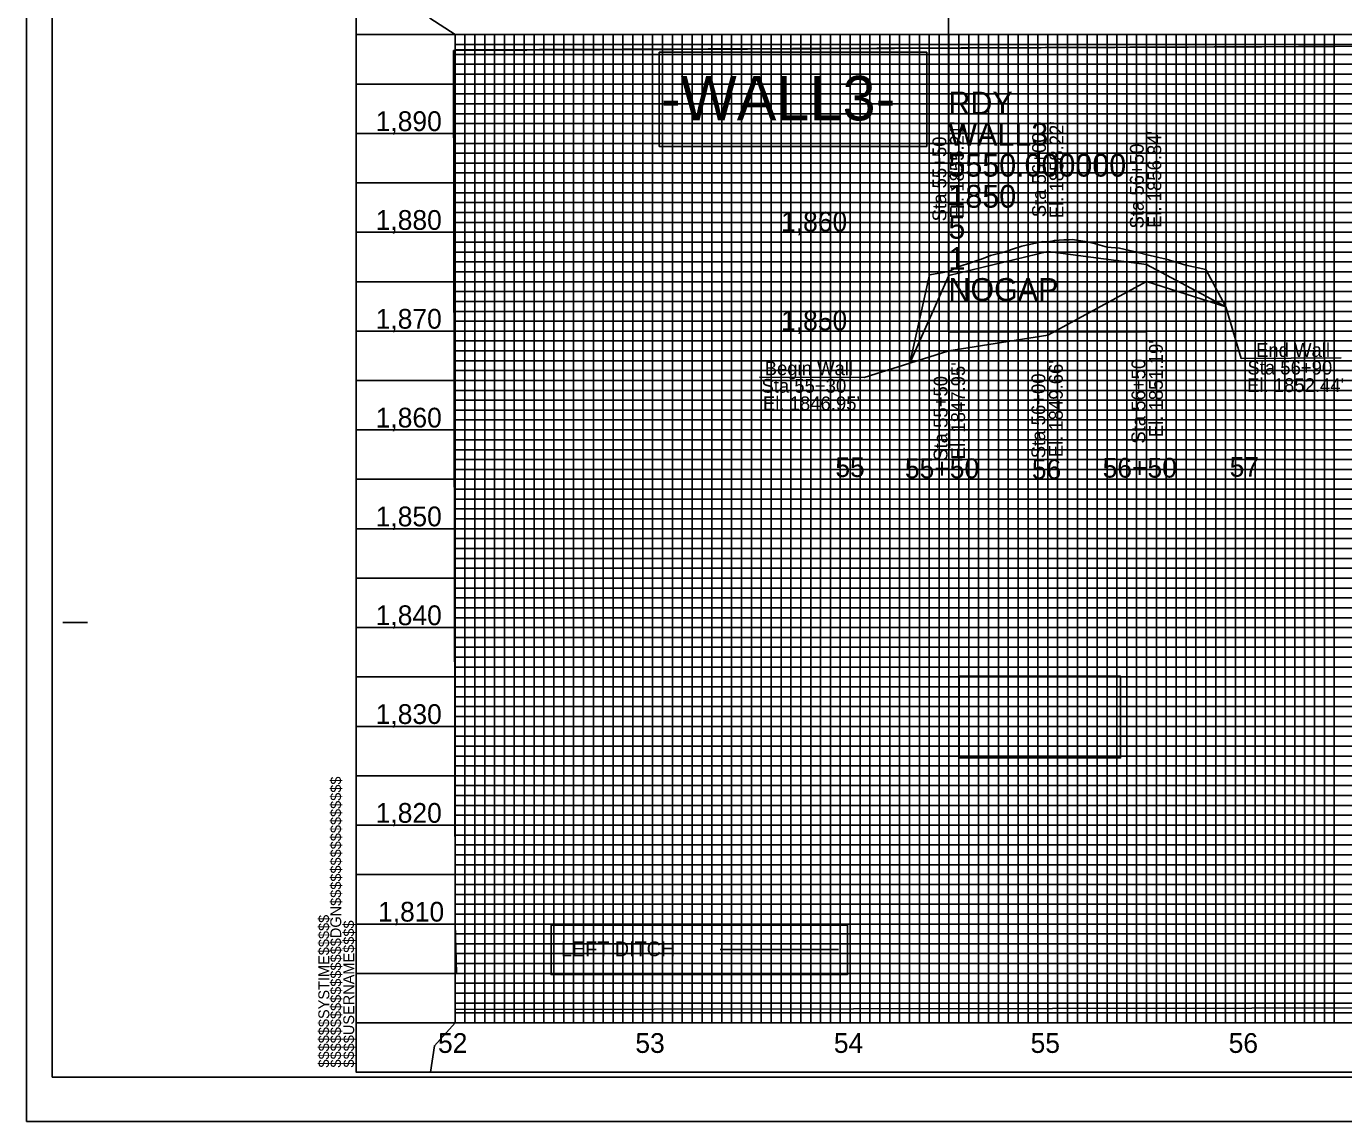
# Model space of a CAD drawing. Extents: x 557032 to 562069, y 513430 to 515874.
# Drawn here: x 557032 to 557699, y 514774 to 515328 of the extents above; entities that cross this region are included whole.
import ezdxf

# ---------------------------------------------------------------- set-up
doc = ezdxf.new("R2010")
doc.units = 0
for name, color, linetype in [('Exist Profile Cell', 7, 'Continuous'), ('Exist Vertical Profile Ground Line', 7, 'Continuous'), ('Exist Vertical Profile Horizontal Axis Label Major', 7, 'Continuous'), ('Exist Vertical Profile Vertical Axis Label', 7, 'Continuous'), ('Prop Grid Mask', 7, 'Continuous'), ('Prop PFL Ditch Label CELL', 7, 'Continuous'), ('Prop Vertical Profile Curve Label', 7, 'Continuous'), ('Prop VPI Label', 7, 'Continuous'), ('Scratch_Level_5', 7, 'Continuous'), ('Sheet Cutting Line CELL', 7, 'Continuous'), ('Sheet DOT Grid CELL', 7, 'Continuous'), ('Sheet Layout Profile Border Port 2', 7, 'Continuous'), ('Sheet Plot Border Inside CELL', 7, 'Continuous'), ('Sheet Plot Border Outside CELL', 7, 'Continuous'), ('Sheet Profile CELL', 7, 'Continuous'), ('Sheet Profile Grid Major CELL', 7, 'Continuous'), ('Sheet Profile Grid Middle CELL', 7, 'Continuous'), ('Sheet Profile Grid Minor CELL', 7, 'Continuous')]:
    doc.layers.add(name, color=color, linetype=linetype)

msp = doc.modelspace()

# ---------------------------------------------------------------- linework, layer by layer
at = {"layer": 'Exist Profile Cell'}
for q in [(557499.18, 515423.85), (557599.7, 515173.85), (557499.18, 515173.85)]:
    msp.add_line((557499.18, 515173.85), q, dxfattribs=at)
at = {"layer": 'Exist Vertical Profile Ground Line'}
for p, q in [((557499.45, 515202.41), (557549.45, 515214.57)), ((557549.45, 515214.57), (557599.45, 515207.95)), ((557599.78, 515212.81), (557609.3, 515210.61)), ((557609.3, 515210.61), (557619.42, 515207.58)), ((557499.45, 515204.38), (557489.6, 515202.69)), ((557599.45, 515207.95), (557639.53, 515186.52)), ((557619.42, 515207.58), (557629.54, 515205.37)), ((557629.54, 515205.37), (557639.53, 515186.52)), ((557489.6, 515202.69), (557479.62, 515157.98)), ((557479.62, 515157.98), (557499.45, 515202.41)), ((557549.45, 515172.19), (557599.45, 515199.37)), ((557599.45, 515199.37), (557639.53, 515186.52)), ((557499.45, 515164.26), (557549.45, 515172.19)), ((557479.62, 515157.98), (557499.45, 515164.26))]:
    msp.add_line(p, q, dxfattribs=at)
msp.add_lwpolyline([(557499.45, 515204.38), (557504.57, 515206.92), (557505.61, 515207.29), (557509.87, 515208.69), (557515.18, 515210.43), (557515.83, 515210.65), (557520.48, 515212.49), (557525.79, 515213.93), (557528.91, 515214.77), (557531.1, 515215.49), (557536.4, 515217.22), (557536.99, 515217.41), (557541.71, 515218.42), (557547.01, 515219.54), (557549.34, 515219.39), (557551.64, 515219.73), (557552.92, 515220.06), (557557.62, 515220.44), (557560.32, 515220.52), (557562.08, 515220.68), (557562.93, 515220.53), (557568.24, 515219.62), (557569.41, 515219.41), (557573.54, 515218.36), (557579.6, 515216.82), (557585.82, 515216.18), (557594.53, 515214.16), (557599.78, 515212.81)], dxfattribs=at)
at = {"layer": 'Prop Grid Mask'}
msp.add_lwpolyline([(557298.05, 514873.67), (557448.05, 514873.67), (557448.05, 514848.67), (557298.05, 514848.67)], close=True, dxfattribs=at)
at = {"layer": 'Prop PFL Ditch Label CELL'}
msp.add_line((557383.6, 514861.37), (557443.6, 514861.37), dxfattribs=at)
at = {"layer": 'Prop Vertical Profile Curve Label'}
for points in [[(557352.78, 515315.36), (557488.16, 515315.36), (557488.16, 515267.69), (557352.78, 515267.69)], [(557504.54, 514999.67), (557586.33, 514999.67), (557586.33, 514958.36), (557504.54, 514958.36)]]:
    msp.add_lwpolyline(points, close=True, dxfattribs=at)
at = {"layer": 'Prop VPI Label'}
for p, q in [((557499.45, 515202.41), (557499.46, 515284.24)), ((557549.45, 515214.57), (557549.46, 515282.16)), ((557599.45, 515207.95), (557599.46, 515279.25)), ((557599.45, 515199.37), (557599.46, 515115.05)), ((557647.41, 515160.47), (557639.53, 515186.52)), ((557549.45, 515172.19), (557549.45, 515109.3)), ((557499.78, 515115.06), (557499.45, 515164.26)), ((557479.62, 515157.98), (557456.45, 515150.8)), ((557697.89, 515160.82), (557647.41, 515160.47)), ((557456.45, 515150.8), (557403.54, 515150.98))]:
    msp.add_line(p, q, dxfattribs=at)
for points in [[(557352.78, 515315.36), (557488.16, 515315.36), (557488.16, 515267.69), (557352.78, 515267.69)], [(557298.05, 514873.67), (557448.05, 514873.67), (557448.05, 514848.67), (557298.05, 514848.67)]]:
    msp.add_lwpolyline(points, close=True, dxfattribs=at)
at = {"layer": 'Scratch_Level_5'}
for p, q in [((557248.74, 515316.3), (557249.51, 514874.14)), ((557249.51, 514874.14), (557250.22, 514849.46))]:
    msp.add_line(p, q, dxfattribs=at)
for points in [[(558499.4, 515824.23), (557249.45, 515849.28), (557249.45, 515349.28), (557236.61, 515332.67), (557249.45, 515324.28), (558649.45, 515324.28), (558662.72, 515334.01), (558649.45, 515349.28), (558649.45, 515688.23), (558499.4, 515688.23)], [(557249.45, 515324.28), (557249.45, 514824.28), (557239, 514812.71), (557236.95, 514799.28), (558647.93, 514799.13), (558699.45, 514799.28), (558649.45, 514824.28), (558649.45, 515324.28)]]:
    msp.add_lwpolyline(points, close=True, dxfattribs=at)
for points in [[(558650.22, 515320.39), (558430.88, 515318.37), (558259.45, 515324.28), (558104.05, 515320.21), (557248.74, 515316.3)], [(557250.22, 514849.46), (558648.7, 514849.31), (558650.22, 514849.32)]]:
    msp.add_lwpolyline(points, dxfattribs=at)
at = {"layer": 'Sheet Cutting Line CELL'}
for p, q in [((557032.45, 515874.28), (557032.45, 514774.28)), ((557032.45, 514774.28), (558716.45, 514774.28))]:
    msp.add_line(p, q, dxfattribs=at)
at = {"layer": 'Sheet DOT Grid CELL'}
for p, q in [((557199.45, 515324.28), (558699.34, 515324.28)), ((557249.45, 515324.28), (557249.45, 514824.28)), ((557299.45, 515324.28), (557299.45, 514824.28)), ((557349.45, 515324.28), (557349.45, 514824.28)), ((557399.45, 515324.28), (557399.45, 514824.28)), ((557449.45, 515324.28), (557449.45, 514824.28)), ((557499.45, 515324.28), (557499.45, 514824.28)), ((557549.45, 515324.28), (557549.45, 514824.28)), ((557649.45, 515324.28), (557649.45, 514824.28)), ((557199.45, 515274.28), (558699.34, 515274.28)), ((557199.45, 515224.28), (558699.34, 515224.28)), ((557199.45, 515174.28), (558699.34, 515174.28)), ((557199.45, 515124.28), (558699.34, 515124.28)), ((557199.45, 515074.28), (558699.34, 515074.28)), ((557199.45, 515024.28), (558699.34, 515024.28)), ((557199.45, 514974.28), (558699.34, 514974.28)), ((557199.45, 514924.28), (558699.34, 514924.28)), ((557199.45, 514874.28), (558699.34, 514874.28))]:
    msp.add_line(p, q, dxfattribs=at)
at = {"layer": 'Sheet Layout Profile Border Port 2'}
msp.add_line((557249.45, 515316.52), (557249.45, 514831.1), dxfattribs=at)
msp.add_lwpolyline([(557249.45, 515324.28), (558649.45, 515324.28), (558649.45, 514824.28), (557249.45, 514824.28)], close=True, dxfattribs=at)
for points in [[(558649.45, 515320.22), (558430.11, 515318.19), (558103.28, 515320.04), (557249.45, 515316.52)], [(557249.45, 514831.1), (558358.41, 514832.88), (558649.45, 514833.95)]]:
    msp.add_lwpolyline(points, dxfattribs=at)
at = {"layer": 'Sheet Plot Border Inside CELL'}
msp.add_lwpolyline([(557045.45, 514796.73), (558711.95, 514796.73), (558711.95, 515851.83), (557045.45, 515851.83)], close=True, dxfattribs=at)
at = {"layer": 'Sheet Plot Border Outside CELL'}
msp.add_lwpolyline([(557032.45, 514774.28), (558716.45, 514774.28), (558716.45, 515874.28), (557032.45, 515874.28)], close=True, dxfattribs=at)
at = {"layer": 'Sheet Profile CELL'}
for p, q in [((557199.45, 515324.28), (558699.45, 515324.28)), ((557050.95, 515026.78), (557063.45, 515026.78)), ((558699.45, 514824.28), (557199.45, 514824.28)), ((557199.45, 514799.28), (558699.45, 514799.28)), ((557199.45, 514799.28), (557199.45, 514799.28)), ((557199.45, 514799.28), (557199.45, 514799.28)), ((557199.45, 514799.28), (557199.45, 514799.28)), ((557199.45, 514799.28), (557199.45, 514799.28)), ((557199.45, 514799.28), (557199.45, 514799.28)), ((557199.45, 514799.28), (557199.45, 514799.28)), ((557199.45, 514799.28), (557199.45, 514799.28))]:
    msp.add_line(p, q, dxfattribs=at)
msp.add_lwpolyline([(558699.45, 515849.28), (557199.45, 515849.28), (557199.45, 514799.28), (558699.45, 514799.28)], close=True, dxfattribs=at)
msp.add_lwpolyline([(557236.95, 514799.28), (557236.95, 514799.28)], dxfattribs=at)
at = {"layer": 'Sheet Profile Grid Major CELL'}
msp.add_line((557199.45, 514824.28), (557199.45, 514824.28), dxfattribs=at)
for points in [[(557249.45, 515324.28), (557249.45, 514824.28), (557299.45, 514824.28), (557299.45, 515324.28), (557349.45, 515324.28), (557349.45, 514824.28), (557399.45, 514824.28), (557399.45, 515324.28), (557449.45, 515324.28), (557449.45, 514824.28), (557499.45, 514824.28), (557499.45, 515324.28), (557549.45, 515324.28), (557549.45, 514824.28), (557599.45, 514824.28), (557599.45, 515324.28), (557649.45, 515324.28), (557649.45, 514824.28), (557699.45, 514824.28)], [(558699.45, 515274.28), (557199.45, 515274.28)], [(558699.45, 515224.28), (557199.45, 515224.28), (557199.45, 515174.28), (558699.45, 515174.28)], [(558699.45, 515124.28), (557199.45, 515124.28), (557199.45, 515074.28), (558699.45, 515074.28)], [(558699.45, 515024.28), (557199.45, 515024.28), (557199.45, 514974.28), (558554.45, 514974.28)], [(558699.45, 514924.28), (557199.45, 514924.28), (557199.45, 514924.28), (557199.45, 514874.28), (558699.45, 514874.28)], [(558699.45, 514824.28), (557199.45, 514824.28)]]:
    msp.add_lwpolyline(points, dxfattribs=at)
at = {"layer": 'Sheet Profile Grid Middle CELL'}
for points in [[(557224.45, 515324.28), (557274.45, 515324.28), (557274.45, 514824.28), (557324.45, 514824.28), (557324.45, 515324.28), (557374.45, 515324.28), (557374.45, 514824.28), (557424.45, 514824.28), (557424.45, 515324.28), (557474.45, 515324.28), (557474.45, 514824.28), (557524.45, 514824.28), (557524.45, 515324.28), (557574.45, 515324.28), (557574.45, 514824.28), (557624.45, 514824.28), (557624.45, 515324.28), (557674.45, 515324.28), (557674.45, 514824.28), (557724.45, 514824.28)], [(557199.45, 515299.28), (558699.45, 515299.28)], [(558699.45, 515249.28), (557199.45, 515249.28), (557199.45, 515199.28), (558699.45, 515199.28)], [(558699.45, 515149.28), (557199.45, 515149.28), (557199.45, 515099.28), (558699.45, 515099.28)], [(558699.45, 515049.28), (557199.45, 515049.28), (557199.45, 514999.28), (558699.45, 514999.28)], [(558699.45, 514949.28), (557199.45, 514949.28), (557199.45, 514899.28), (558699.45, 514899.28)], [(558699.45, 514849.28), (557199.45, 514849.28)]]:
    msp.add_lwpolyline(points, dxfattribs=at)
at = {"layer": 'Sheet Profile Grid Minor CELL'}
for p, q in [((557249.45, 515319.28), (558649.45, 515319.28)), ((558649.45, 515314.28), (557249.45, 515314.28)), ((557249.45, 515309.28), (558649.45, 515309.28)), ((558649.45, 515304.28), (557249.45, 515304.28)), ((557249.45, 515294.28), (558649.45, 515294.28)), ((558649.45, 515289.28), (557249.45, 515289.28)), ((557249.45, 515284.28), (558649.45, 515284.28)), ((558649.45, 515279.28), (557249.45, 515279.28)), ((557249.45, 515269.28), (558649.45, 515269.28)), ((558649.45, 515264.28), (557249.45, 515264.28)), ((557249.45, 515259.28), (558649.45, 515259.28)), ((558649.45, 515254.28), (557249.45, 515254.28)), ((557249.45, 515244.28), (558649.45, 515244.28)), ((558649.45, 515239.28), (557249.45, 515239.28)), ((557249.45, 515234.28), (558649.45, 515234.28)), ((558649.45, 515229.28), (557249.45, 515229.28)), ((557249.45, 515219.28), (558649.45, 515219.28)), ((558649.45, 515214.28), (557249.45, 515214.28)), ((557249.45, 515209.28), (558649.45, 515209.28)), ((558649.45, 515204.28), (557249.45, 515204.28)), ((557249.45, 515194.28), (558649.45, 515194.28)), ((558649.45, 515189.28), (557249.45, 515189.28)), ((557249.45, 515184.28), (558649.45, 515184.28)), ((558649.45, 515179.28), (557249.45, 515179.28)), ((557249.45, 515169.28), (558649.45, 515169.28)), ((558649.45, 515164.28), (557249.45, 515164.28)), ((557249.45, 515159.28), (558649.45, 515159.28)), ((558649.45, 515154.28), (557249.45, 515154.28)), ((557249.45, 515144.28), (558649.45, 515144.28)), ((558649.45, 515139.28), (557249.45, 515139.28)), ((557249.45, 515134.28), (558649.45, 515134.28)), ((558649.45, 515129.28), (557249.45, 515129.43)), ((557249.45, 515119.28), (558649.45, 515119.28)), ((558649.45, 515114.28), (557249.45, 515114.28)), ((557249.45, 515109.28), (558649.45, 515109.28)), ((558649.45, 515104.28), (557249.45, 515104.28)), ((557249.45, 515094.28), (558649.45, 515094.28)), ((558649.45, 515089.28), (557249.45, 515089.28)), ((557249.45, 515084.28), (558649.45, 515084.28)), ((558649.45, 515079.28), (557249.45, 515079.28)), ((557249.45, 515069.28), (558649.45, 515069.28)), ((558649.45, 515064.28), (557249.45, 515064.28)), ((557249.45, 515059.28), (558649.45, 515059.28)), ((558649.45, 515054.28), (557249.45, 515054.28)), ((557249.45, 515044.28), (558649.45, 515044.28)), ((558649.45, 515039.28), (557249.45, 515039.28)), ((557249.45, 515034.28), (558649.45, 515034.28)), ((558649.45, 515029.28), (557249.45, 515029.28)), ((557249.45, 515019.28), (558649.45, 515019.28)), ((558649.45, 515014.28), (557249.45, 515014.28)), ((557249.45, 515009.28), (558649.45, 515009.28)), ((558649.45, 515004.28), (557249.45, 515004.28)), ((557249.45, 514994.28), (558649.45, 514994.28)), ((558554.45, 514989.28), (557249.45, 514989.28)), ((557249.45, 514984.28), (558554.45, 514984.28)), ((558554.45, 514979.28), (557249.45, 514979.28)), ((557249.45, 514969.28), (558554.45, 514969.28)), ((558649.45, 514964.28), (557249.45, 514964.28)), ((557249.45, 514959.28), (558649.45, 514959.28)), ((558649.45, 514954.28), (557249.45, 514954.28)), ((557249.45, 514944.28), (558649.45, 514944.28)), ((558649.45, 514939.28), (557249.45, 514939.28)), ((557249.45, 514934.28), (558649.45, 514934.28)), ((558649.45, 514929.28), (557249.45, 514929.28)), ((557249.45, 514919.28), (558649.45, 514919.28)), ((558649.45, 514914.28), (557249.45, 514914.28)), ((557249.45, 514909.28), (558649.45, 514909.28)), ((558649.45, 514904.28), (557249.45, 514904.28)), ((557249.45, 514894.28), (558649.45, 514894.28)), ((558649.45, 514889.28), (557249.45, 514889.28)), ((557249.45, 514884.28), (558649.45, 514884.28)), ((558649.45, 514879.28), (557249.45, 514879.28)), ((557249.45, 514869.28), (558649.45, 514869.28)), ((558649.45, 514864.28), (557249.45, 514864.28)), ((557249.45, 514859.28), (558649.45, 514859.28)), ((558649.45, 514854.28), (557249.45, 514854.28)), ((557249.45, 514844.28), (558649.45, 514844.28)), ((558649.45, 514839.28), (557249.45, 514839.28)), ((557249.45, 514834.28), (558649.45, 514834.28)), ((557249.45, 514829.28), (558649.45, 514829.28))]:
    msp.add_line(p, q, dxfattribs=at)
for points in [[(557249.45, 515324.28), (557254.45, 515324.28), (557254.45, 514824.28), (557259.45, 514824.28), (557259.45, 515324.28), (557264.45, 515324.28), (557264.45, 514824.28), (557269.45, 514824.28), (557269.45, 515324.28), (557279.45, 515324.28), (557279.45, 514824.28), (557284.45, 514824.28), (557284.45, 515324.28), (557289.45, 515324.28), (557289.45, 514824.28), (557294.45, 514824.28), (557304.45, 514824.28), (557309.45, 514824.28), (557309.45, 515324.28), (557314.45, 515324.28), (557314.45, 514824.28), (557319.45, 514824.28), (557319.45, 515324.28), (557329.45, 515324.28), (557329.45, 514824.28), (557334.45, 514824.28), (557334.45, 515324.28), (557339.45, 515324.28), (557339.45, 514824.28), (557344.45, 514824.28), (557344.45, 515324.28), (557354.45, 515324.28), (557354.45, 514824.28), (557359.45, 514824.28), (557359.45, 515324.28), (557364.45, 515324.28), (557364.45, 514824.28), (557369.45, 514824.28), (557369.45, 515324.28), (557379.45, 515324.28), (557379.45, 514824.28), (557384.45, 514824.28), (557384.45, 515324.28), (557389.45, 515324.28), (557389.45, 514824.28), (557394.45, 514824.28), (557394.45, 515324.28), (557404.45, 515324.28), (557404.45, 514824.28), (557409.45, 514824.28), (557409.45, 515324.28), (557414.45, 515324.28), (557414.45, 514824.28), (557419.45, 514824.28), (557419.45, 515324.28), (557429.45, 515324.28), (557429.45, 514824.28), (557434.45, 514824.28), (557434.45, 515324.28), (557439.45, 515324.28), (557439.45, 514824.28), (557444.45, 514824.28), (557444.45, 515324.28), (557454.45, 515324.28), (557454.45, 514824.28), (557459.45, 514824.28), (557459.45, 515324.28), (557464.45, 515324.28), (557464.45, 514824.28)], [(557294.45, 514824.28), (557294.45, 515324.28), (557304.45, 515324.28), (557304.45, 514824.28)], [(557464.45, 514824.28), (557469.45, 514824.28), (557469.45, 515324.28), (557479.45, 515324.28), (557479.45, 514824.28), (557484.45, 514824.28), (557484.45, 515324.28), (557489.45, 515324.28), (557489.45, 514824.28), (557494.45, 514824.28), (557494.45, 515324.28), (557504.45, 515324.28), (557504.45, 514824.28), (557509.45, 514824.28), (557509.45, 515324.28), (557514.45, 515324.28), (557514.45, 514824.28), (557519.45, 514824.28), (557519.45, 515324.28), (557529.45, 515324.28), (557529.45, 514824.28), (557534.45, 514824.28), (557534.45, 515324.28), (557539.45, 515324.28), (557539.45, 514824.28), (557544.45, 514824.28), (557544.45, 515324.28), (557554.45, 515324.28), (557554.45, 514824.28), (557559.45, 514824.28), (557559.45, 515324.28), (557564.45, 515324.28), (557564.45, 514824.28), (557569.45, 514824.28), (557569.45, 515324.28), (557579.45, 515324.28), (557579.45, 514824.28), (557584.45, 514824.28), (557584.45, 515324.28), (557589.45, 515324.28), (557589.45, 514824.28), (557594.45, 514824.28), (557594.45, 515324.28), (557604.45, 515324.28), (557604.45, 514824.28), (557609.45, 514824.28), (557609.45, 515324.28), (557614.45, 515324.28), (557614.45, 514824.28), (557619.45, 514824.28), (557619.45, 515324.28), (557629.45, 515324.28), (557629.45, 514824.28), (557634.45, 514824.28), (557634.45, 515324.28), (557639.45, 515324.28), (557639.45, 514824.28), (557644.45, 514824.28), (557644.45, 515324.28), (557654.45, 515324.28), (557654.45, 514824.28), (557659.45, 514824.28), (557659.45, 515324.28), (557664.45, 515324.28), (557664.45, 514824.28), (557669.45, 514824.28), (557669.45, 515324.28), (557679.45, 515324.28), (557679.45, 514824.28), (557684.45, 514824.28), (557684.45, 515324.28), (557689.45, 515324.28), (557689.45, 514824.28), (557694.45, 514824.28), (557694.45, 515324.28), (557704.45, 515324.28)]]:
    msp.add_lwpolyline(points, dxfattribs=at)

# ---------------------------------------------------------------- texts
at = {"layer": 'Exist Profile Cell'}
for s, p in [('RDY', (557499.18, 515283.89)), ('WALL3', (557499.18, 515268.17)), ('5550.000000', (557499.18, 515252.45)), ('1850', (557499.18, 515236.73)), ('5', (557499.18, 515221.01)), ('1', (557499.18, 515205.29)), ('NOGAP', (557499.18, 515189.57))]:
    msp.add_text(s, height=11.52, dxfattribs=at).set_placement(p)
at = {"layer": 'Exist Vertical Profile Horizontal Axis Label Major'}
for s, p in [('55', (557441.94, 515100.46)), ('55+50', (557477.15, 515099.85)), ('56+50', (557577.23, 515100.14)), ('57', (557641.52, 515100.55)), ('56', (557541.4, 515099.41)), ('52', (557240.82, 514809.06)), ('53', (557340.71, 514809.06)), ('54', (557441.18, 514809.06)), ('55', (557540.76, 514809.06)), ('56', (557641.02, 514809.06))]:
    msp.add_text(s, height=10, dxfattribs=at).set_placement(p)
at = {"layer": 'Exist Vertical Profile Vertical Axis Label'}
for s, p in [('1,890', (557209.27, 515275.5)), ('1,890', (557209.27, 515275.5)), ('1,880', (557209.27, 515225.5)), ('1,880', (557209.27, 515225.5)), ('1,860', (557414.46, 515224.67)), ('1,870', (557209.27, 515175.5)), ('1,870', (557209.27, 515175.5)), ('1,850', (557414.46, 515174.67)), ('1,860', (557209.27, 515125.5)), ('1,860', (557209.27, 515125.5)), ('1,850', (557209.27, 515075.5)), ('1,850', (557209.27, 515075.5)), ('1,840', (557209.27, 515025.5)), ('1,840', (557209.27, 515025.5)), ('1,830', (557209.27, 514975.5)), ('1,830', (557209.27, 514975.5)), ('1,820', (557209.27, 514925.5)), ('1,820', (557209.27, 514925.5)), ('1,810', (557210.47, 514875.5)), ('1,810', (557210.47, 514875.5))]:
    msp.add_text(s, height=10, dxfattribs=at).set_placement(p)
at = {"layer": 'Prop PFL Ditch Label CELL'}
msp.add_text('LEFT DITCH', height=7.485, dxfattribs=at).set_placement((557303.05, 514857.97))
at = {"layer": 'Prop Vertical Profile Curve Label'}
msp.add_text('-WALL3-', height=22.5, dxfattribs=at).set_placement((557353.62, 515280.9))
at = {"layer": 'Prop VPI Label'}
for s, rotation, p in [("El. 1855.21'", 90, (557506.96, 515231.27)), ("El. 1858.22'", 90, (557557.37, 515231.35)), ('Sta 55+50', 90, (557498.09, 515229.81)), ('Sta 56+00', 90, (557548.5, 515231.88)), ("El. 1856.84'", 90, (557606.91, 515226.44)), ('Sta 56+50', 90, (557598.03, 515226.19)), ("El. 1851.19'", 90, (557607.71, 515120.56)), ('End Wall', 360, (557654.88, 515161.19)), ("El. 1847.95'", 90, (557507.57, 515109.38)), ("El. 1849.66'", 90, (557557.06, 515110.41)), ('Sta 56+50', 90, (557598.84, 515117.33)), ('Sta 56+90', 360, (557650.5, 515152.32)), ('Sta 55+50', 90, (557498.7, 515108.63)), ('Sta 56+00', 90, (557548.19, 515109.94)), ("El. 1852.44'", 360, (557650.31, 515143.44))]:
    msp.add_text(s, height=7, rotation=rotation, dxfattribs=at).set_placement(p)
for s, p in [('Begin Wall', (557406.16, 515151.97)), ('Sta 55+30', (557404.53, 515143.1)), ("El. 1846.95'", (557405.28, 515134.22))]:
    msp.add_text(s, height=7, dxfattribs=at).set_placement(p)
at = {"layer": 'Sheet Profile CELL'}
for s, p in [('$$$$$$$$$$$$$$$$DGN$$$$$$$$$$$$$$$$', (557191.82, 514801.66)), ('$$$$$$SYSTIME$$$$$', (557185.77, 514801.66)), ('$$$$USERNAME$$$$', (557198.39, 514801.67))]:
    msp.add_text(s, height=5.5, rotation=90, dxfattribs=at).set_placement(p)

doc.saveas('drawing.dxf')
